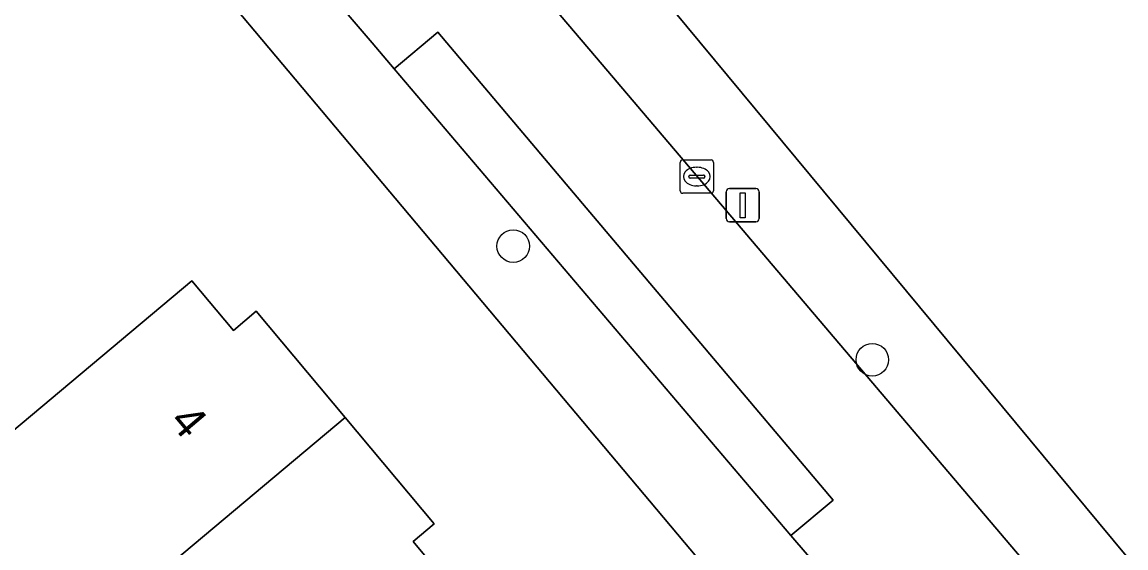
# Model space of a CAD drawing. Extents: x 161772 to 163126, y 383092 to 383917.
# Drawn here: x 162023.56 to 162056.73, y 383429.21 to 383445 of the extents above; entities that cross this region are included whole.
import ezdxf

# ---------------------------------------------------------------- set-up
doc = ezdxf.new("R2010")
doc.units = 0
for name, color, linetype in [('IMGEO_Boom', 7, 'Continuous'), ('IMGEO_Erf', 7, 'Continuous'), ('IMGEO_Kolk', 7, 'Continuous'), ('IMGEO_Lichtmast', 7, 'Continuous'), ('IMGEO_Pand', 7, 'Continuous'), ('IMGEO_Pand_nummerreeks', 7, 'Continuous'), ('IMGEO_Parkeervlak_open', 7, 'Continuous'), ('IMGEO_Rijbaan_lokaal_open', 7, 'Continuous'), ('IMGEO_Voetpad_gesloten', 7, 'Continuous')]:
    doc.layers.add(name, color=color, linetype=linetype)

msp = doc.modelspace()

# ---------------------------------------------------------------- linework, layer by layer
at = {"layer": 'IMGEO_Boom'}
for centre in [(162038.32, 383438.275), (162049.106, 383434.863)]:
    msp.add_circle(centre, 0.489, dxfattribs=at)
at = {"layer": 'IMGEO_Erf'}
for points in [[(162100.337, 383471.381), (162086.524, 383472.415), (162082.905, 383472.362), (162043.107, 383468.003), (162027.495, 383466.15), (162027.9, 383463.647), (162030.791, 383459.92), (162042.704, 383445.878), (162056.737, 383428.976), (162069.531, 383413.985), (162082.036, 383400.151), (162085.851, 383396.183), (162119.667, 383362.459)], [(161988.831, 383383.094), (161989.798, 383375.666), (161990.795, 383374.566), (161992.579, 383373.341), (161993.75, 383372.87), (162001.33, 383371.327), (162032.857, 383365.301), (162067.97, 383400.221), (162013.474, 383465.049)], [(162017.568, 383427.062), (162015.416, 383433.658), (162018.614, 383436.338), (162022.319, 383431.917), (162028.664, 383437.233), (162029.911, 383435.745), (162030.599, 383436.321), (162033.275, 383433.128), (162035.949, 383429.937), (162035.309, 383429.401), (162036.507, 383427.971)]]:
    msp.add_lwpolyline(points, dxfattribs=at)
at = {"layer": 'IMGEO_Kolk'}
for p, q in [((162043.335, 383439.938), (162043.335, 383440.79)), ((162043.41, 383440.864), (162044.262, 383440.864)), ((162043.823, 383440.644), (162043.848, 383440.644)), ((162044.336, 383440.79), (162044.336, 383439.938)), ((162043.594, 383440.358), (162043.594, 383440.37)), ((162044.032, 383440.321), (162043.634, 383440.321)), ((162043.637, 383440.407), (162044.035, 383440.407)), ((162044.078, 383440.37), (162044.078, 383440.358)), ((162043.846, 383440.084), (162043.821, 383440.084)), ((162044.262, 383439.864), (162043.41, 383439.864))]:
    msp.add_line(p, q, dxfattribs=at)
for points in [[(162043.335, 383439.938), (162043.335, 383440.79)], [(162043.41, 383440.864), (162044.262, 383440.864)], [(162044.336, 383440.79), (162044.336, 383439.938)], [(162044.262, 383439.864), (162043.41, 383439.864)]]:
    msp.add_lwpolyline(points, dxfattribs=at)
for centre, radius, start, end in [((162043.412, 383440.788), 0.0765, 91.552, 178.448), ((162043.412, 383440.788), 0.0765, 91.552, 178.448), ((162044.26, 383440.788), 0.0765, 1.552, 88.448), ((162044.26, 383440.788), 0.0765, 1.552, 88.448), ((162043.634, 383440.367), 0.0403, 85.8775, 175.7526), ((162043.631, 383440.357), 0.0366, 178.938, 274.7102), ((162044.035, 383440.364), 0.043, 264.8664, 352.4533), ((162044.039, 383440.369), 0.0386, 1.7309, 96.639), ((162043.412, 383439.94), 0.0765, 181.552, 268.448), ((162043.412, 383439.94), 0.0765, 181.552, 268.448), ((162044.26, 383439.94), 0.0765, 271.552, 358.448), ((162044.26, 383439.94), 0.0765, 271.552, 358.448)]:
    msp.add_arc(centre, radius, start, end, dxfattribs=at)
for centre, major_axis, ratio, start_param, end_param in [((162043.822, 383440.364), (-0.387, 0.002), 0.722429, 4.712389, 7.853982), ((162043.847, 383440.364), (-0.39, 0.002), 0.717154, 1.570796, 4.712389)]:
    msp.add_ellipse(centre, major_axis=major_axis, ratio=ratio, start_param=start_param, end_param=end_param, dxfattribs=at)
at = {"layer": 'IMGEO_Lichtmast'}
for p, q in [((162044.82, 383440.003), (162045.61, 383440.003)), ((162045.61, 383440.003), (162044.82, 383440.003)), ((162044.72, 383439.103), (162044.72, 383439.903)), ((162044.72, 383439.903), (162044.72, 383439.103)), ((162045.71, 383439.903), (162045.71, 383439.103)), ((162045.71, 383439.103), (162045.71, 383439.903)), ((162045.61, 383439.003), (162044.82, 383439.003)), ((162044.82, 383439.003), (162045.61, 383439.003))]:
    msp.add_line(p, q, dxfattribs=at)
msp.add_lwpolyline([(162045.14, 383439.878), (162045.29, 383439.878), (162045.29, 383439.128), (162045.14, 383439.128), (162045.14, 383439.878)], dxfattribs=at)
for centre, start, end in [((162044.82, 383439.903), 90, 180), ((162044.82, 383439.903), 90, 180), ((162045.61, 383439.903), 0, 90), ((162045.61, 383439.903), 360, 90), ((162044.82, 383439.103), 180, 270), ((162044.82, 383439.103), 180, 270), ((162045.61, 383439.103), 270, 0), ((162045.61, 383439.103), 270, 0)]:
    msp.add_arc(centre, 0.1, start, end, dxfattribs=at)
at = {"layer": 'IMGEO_Pand'}
for points in [[(162025.074, 383426.256), (162033.275, 383433.128), (162030.599, 383436.321), (162029.911, 383435.745), (162028.664, 383437.233), (162022.319, 383431.917), (162018.614, 383436.338), (162015.416, 383433.658), (162017.568, 383427.062), (162018.761, 383428.061), (162020.444, 383426.053), (162023.264, 383428.416)], [(162025.074, 383426.256), (162027.133, 383423.799), (162023.645, 383420.877), (162025.456, 383418.715), (162036.507, 383427.971), (162035.309, 383429.401), (162035.949, 383429.937), (162033.275, 383433.128)]]:
    msp.add_lwpolyline(points, close=True, dxfattribs=at)
at = {"layer": 'IMGEO_Parkeervlak_open'}
msp.add_lwpolyline([(162034.744, 383443.6), (162046.657, 383429.59), (162047.931, 383430.647), (162043.957, 383435.348), (162040.018, 383440.006), (162036.054, 383444.697)], close=True, dxfattribs=at)
at = {"layer": 'IMGEO_Rijbaan_lokaal_open'}
msp.add_lwpolyline([(162040.822, 383443.925), (162038.41, 383446.77), (162034.776, 383451.058), (162031.033, 383447.948), (162031.679, 383447.192), (162034.081, 383444.38), (162034.744, 383443.6), (162036.054, 383444.697), (162040.018, 383440.006), (162043.957, 383435.348), (162047.931, 383430.647), (162046.657, 383429.59), (162047.148, 383429.013), (162049.56, 383426.147), (162050.138, 383425.46), (162051.448, 383426.528), (162055.02, 383422.31), (162058.355, 383418.369), (162060.745, 383420.481)], close=True, dxfattribs=at)
at = {"layer": 'IMGEO_Voetpad_gesloten'}
for points in [[(162019.777, 383466.499), (162013.474, 383465.049), (162067.97, 383400.221), (162069.608, 383398.523), (162069.956, 383398.861), (162070.285, 383399.377)], [(162085.851, 383396.183), (162082.036, 383400.151), (162069.531, 383413.985), (162056.737, 383428.976), (162042.704, 383445.878), (162030.791, 383459.92), (162027.9, 383463.647), (162027.495, 383466.15), (162024.547, 383465.773)], [(162025.575, 383461.853), (162027.191, 383459.927), (162028.008, 383458.961), (162032.937, 383453.211), (162034.192, 383451.747), (162034.776, 383451.058), (162038.41, 383446.77), (162040.822, 383443.925), (162060.745, 383420.481), (162062.563, 383418.343), (162071.059, 383408.345), (162073.542, 383405.497), (162076.743, 383402.112), (162077.699, 383401.158), (162089.151, 383389.723)], [(162034.744, 383443.6), (162034.081, 383444.38), (162031.679, 383447.192), (162031.033, 383447.948), (162029.195, 383450.109), (162027.544, 383452.055), (162024.525, 383455.612), (162024.128, 383456.084), (162023.946, 383456.646), (162024.006, 383458.096)], [(162070.451, 383400.958), (162070.146, 383401.685), (162058.872, 383415.082), (162057.064, 383417.229), (162050.138, 383425.46), (162049.56, 383426.147), (162047.148, 383429.013), (162046.657, 383429.59), (162034.744, 383443.6)]]:
    msp.add_lwpolyline(points, dxfattribs=at)

# ---------------------------------------------------------------- texts
at = {"layer": 'IMGEO_Pand_nummerreeks'}
msp.add_text('4', height=1, rotation=310.2573, dxfattribs=at).set_placement((162027.956, 383432.993))

doc.saveas('drawing.dxf')
